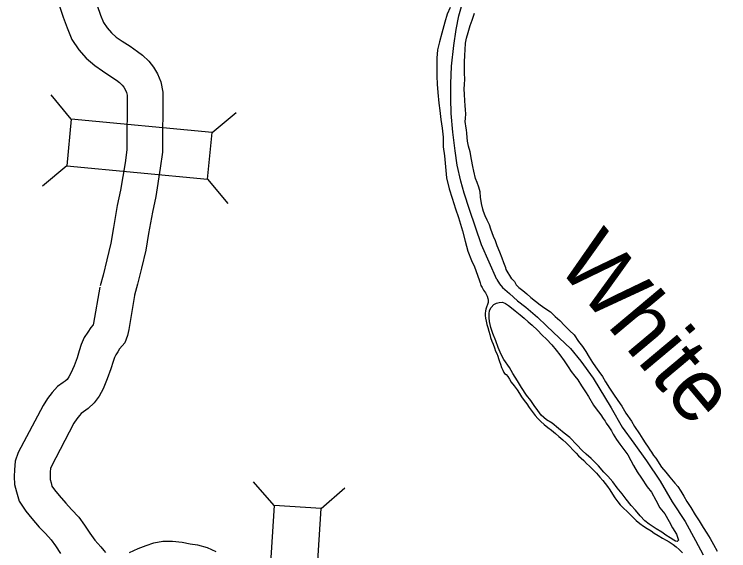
# Model space of a CAD drawing. Extents: x 1377389 to 1380723, y 1168351 to 1170484.
# Drawn here: x 1377843.3 to 1377903.4, y 1169705.3 to 1169750.4 of the extents above; entities that cross this region are included whole.
import ezdxf

# ---------------------------------------------------------------- set-up
doc = ezdxf.new("R2010")
doc.units = 0
doc.layers.add('B_Fill', color=7, linetype='Continuous')

msp = doc.modelspace()

# ---------------------------------------------------------------- linework, layer by layer
at = {"layer": 'B_Fill'}
for p, q in [((1377848.125, 1169741.601), (1377846.442, 1169743.635)), ((1377859.952, 1169740.483), (1377861.986, 1169742.165)), ((1377847.752, 1169737.658), (1377845.718, 1169735.975)), ((1377859.579, 1169736.54), (1377861.262, 1169734.506)), ((1377865.17, 1169709.11), (1377863.426, 1169711.092)), ((1377869.122, 1169708.858), (1377871.104, 1169710.603))]:
    msp.add_line(p, q, dxfattribs=at)
for points in [[(1377847.062, 1169751.354), (1377847.452, 1169750.17), (1377847.773, 1169749.278), (1377848.162, 1169748.289), (1377848.769, 1169747.424), (1377849.376, 1169746.72), (1377850.089, 1169746.099), (1377850.751, 1169745.665), (1377851.374, 1169745.248), (1377851.919, 1169744.863), (1377852.172, 1169744.669), (1377852.397, 1169744.464), (1377852.53, 1169744.285), (1377852.688, 1169744.022), (1377852.769, 1169743.839), (1377852.811, 1169743.604), (1377852.792, 1169739.027), (1377852.637, 1169737.924), (1377852.268, 1169735.637), (1377851.991, 1169734.336), (1377851.661, 1169732.484), (1377851.45, 1169731.174), (1377851.121, 1169729.776), (1377850.789, 1169728.486), (1377850.546, 1169727.593)], [(1377850.289, 1169751.148), (1377850.581, 1169750.335), (1377850.823, 1169749.719), (1377851.138, 1169749.27), (1377851.507, 1169748.842), (1377851.905, 1169748.496), (1377852.408, 1169748.165), (1377853.074, 1169747.72), (1377853.695, 1169747.281), (1377854.098, 1169746.973), (1377854.636, 1169746.482), (1377855.026, 1169745.955), (1377855.353, 1169745.411), (1377855.659, 1169744.724), (1377855.812, 1169743.862), (1377855.792, 1169738.81), (1377855.603, 1169737.475), (1377855.218, 1169735.085), (1377854.936, 1169733.761), (1377854.619, 1169731.982), (1377854.395, 1169730.591), (1377854.034, 1169729.058), (1377853.689, 1169727.719), (1377853.441, 1169726.806)], [(1377883.88, 1169728.123), (1377882.593, 1169731.028), (1377881.579, 1169734.004), (1377881.116, 1169735.373), (1377880.844, 1169736.388), (1377880.531, 1169737.731), (1377880.364, 1169738.929), (1377880.175, 1169740.488), (1377880.045, 1169742.068), (1377880.006, 1169743.321), (1377879.997, 1169744.574), (1377880.06, 1169746.06), (1377880.247, 1169747.781), (1377880.445, 1169749.121), (1377880.669, 1169750.291), (1377881.012, 1169751.456)], [(1377879.956, 1169750.981), (1377879.704, 1169750.411), (1377879.504, 1169749.753), (1377879.264, 1169748.812), (1377879.056, 1169748.104), (1377878.896, 1169747.437), (1377878.839, 1169746.713), (1377878.819, 1169746.061), (1377878.826, 1169745.208), (1377878.857, 1169744.527), (1377878.919, 1169743.827), (1377879.007, 1169742.948), (1377879.077, 1169742.318), (1377879.18, 1169741.579), (1377879.293, 1169740.831), (1377879.367, 1169740.091), (1377879.372, 1169739.269), (1377879.466, 1169738.5), (1377879.644, 1169736.67), (1377879.873, 1169735.745), (1377880.118, 1169734.96), (1377880.396, 1169734.057), (1377880.659, 1169733.323), (1377880.975, 1169732.2), (1377881.222, 1169731.325), (1377881.449, 1169730.49), (1377881.744, 1169729.697), (1377881.99, 1169729.174), (1377882.39, 1169728.082)], [(1377879.956, 1169750.981), (1377879.704, 1169750.411), (1377879.504, 1169749.753), (1377879.264, 1169748.812), (1377879.056, 1169748.104), (1377878.896, 1169747.437), (1377878.839, 1169746.713), (1377878.819, 1169746.061), (1377878.826, 1169745.208), (1377878.857, 1169744.527), (1377878.919, 1169743.827), (1377879.007, 1169742.948), (1377879.077, 1169742.318), (1377879.18, 1169741.579), (1377879.293, 1169740.831), (1377879.367, 1169740.091), (1377879.372, 1169739.269), (1377879.466, 1169738.5), (1377879.644, 1169736.67), (1377879.873, 1169735.745), (1377880.118, 1169734.96), (1377880.396, 1169734.057), (1377880.659, 1169733.323), (1377880.975, 1169732.2), (1377881.222, 1169731.325), (1377881.449, 1169730.49), (1377881.744, 1169729.697), (1377881.99, 1169729.174), (1377882.39, 1169728.082)], [(1377885.13, 1169728.177), (1377884.65, 1169728.948), (1377884.615, 1169729.107), (1377884.452, 1169729.513), (1377884.309, 1169729.91), (1377884.123, 1169730.415), (1377883.907, 1169730.94), (1377883.753, 1169731.356), (1377883.592, 1169731.732), (1377883.382, 1169732.337), (1377883.251, 1169732.704), (1377883.059, 1169733.089), (1377882.896, 1169733.475), (1377882.765, 1169733.831), (1377882.689, 1169734.03), (1377882.574, 1169734.507), (1377882.507, 1169735.047), (1377882.463, 1169735.497), (1377882.371, 1169735.885), (1377882.218, 1169736.271), (1377882.087, 1169736.618), (1377881.949, 1169737.215), (1377881.856, 1169737.613), (1377881.758, 1169738.202), (1377881.628, 1169738.839), (1377881.502, 1169739.327), (1377881.409, 1169739.735), (1377881.38, 1169740.045), (1377881.358, 1169740.425), (1377881.319, 1169740.705), (1377881.295, 1169740.845), (1377881.217, 1169741.394), (1377881.23, 1169741.645), (1377881.257, 1169742.047), (1377881.247, 1169742.367), (1377881.215, 1169742.757), (1377881.193, 1169743.128), (1377881.155, 1169743.708), (1377881.132, 1169744.119), (1377881.159, 1169744.551), (1377881.177, 1169744.932), (1377881.169, 1169745.504), (1377881.144, 1169745.974), (1377881.161, 1169746.386), (1377881.182, 1169746.988), (1377881.199, 1169747.42), (1377881.232, 1169747.973), (1377881.328, 1169748.417), (1377881.474, 1169748.873), (1377881.625, 1169749.46), (1377881.791, 1169749.916), (1377881.993, 1169750.504)], [(1377885.13, 1169728.177), (1377884.65, 1169728.948), (1377884.615, 1169729.107), (1377884.452, 1169729.513), (1377884.309, 1169729.91), (1377884.123, 1169730.415), (1377883.907, 1169730.94), (1377883.753, 1169731.356), (1377883.592, 1169731.732), (1377883.382, 1169732.337), (1377883.251, 1169732.704), (1377883.059, 1169733.089), (1377882.896, 1169733.475), (1377882.765, 1169733.831), (1377882.689, 1169734.03), (1377882.574, 1169734.507), (1377882.507, 1169735.047), (1377882.463, 1169735.497), (1377882.371, 1169735.885), (1377882.218, 1169736.271), (1377882.087, 1169736.618), (1377881.949, 1169737.215), (1377881.856, 1169737.613), (1377881.758, 1169738.202), (1377881.628, 1169738.839), (1377881.502, 1169739.327), (1377881.409, 1169739.735), (1377881.38, 1169740.045), (1377881.358, 1169740.425), (1377881.319, 1169740.705), (1377881.295, 1169740.845), (1377881.217, 1169741.394), (1377881.23, 1169741.645), (1377881.257, 1169742.047), (1377881.247, 1169742.367), (1377881.215, 1169742.757), (1377881.193, 1169743.128), (1377881.155, 1169743.708), (1377881.132, 1169744.119), (1377881.159, 1169744.551), (1377881.177, 1169744.932), (1377881.169, 1169745.504), (1377881.144, 1169745.974), (1377881.161, 1169746.386), (1377881.182, 1169746.988), (1377881.199, 1169747.42), (1377881.232, 1169747.973), (1377881.328, 1169748.417), (1377881.474, 1169748.873), (1377881.625, 1169749.46), (1377881.791, 1169749.916), (1377881.993, 1169750.504)], [(1377882.39, 1169728.082), (1377882.466, 1169727.834), (1377882.542, 1169727.615), (1377882.637, 1169727.427), (1377882.753, 1169727.209), (1377882.909, 1169726.993), (1377883.056, 1169726.726), (1377883.112, 1169726.517), (1377883.145, 1169726.367), (1377883.14, 1169726.177), (1377883.085, 1169726.004), (1377883.011, 1169725.782), (1377882.945, 1169725.609), (1377882.919, 1169725.478), (1377882.894, 1169725.257), (1377882.889, 1169725.096), (1377882.915, 1169724.866), (1377882.972, 1169724.597), (1377883.039, 1169724.338), (1377883.116, 1169724.069), (1377883.194, 1169723.77), (1377883.271, 1169723.502), (1377883.348, 1169723.223), (1377883.456, 1169722.935), (1377883.553, 1169722.666), (1377883.671, 1169722.359), (1377883.768, 1169722.1), (1377883.873, 1169721.893), (1377883.959, 1169721.674), (1377884.025, 1169721.475), (1377884.101, 1169721.217), (1377884.177, 1169720.988), (1377884.265, 1169720.719), (1377884.371, 1169720.482), (1377884.456, 1169720.293), (1377884.528, 1169720.215), (1377884.651, 1169720.118), (1377884.785, 1169719.971), (1377884.931, 1169719.724), (1377885.088, 1169719.488), (1377885.336, 1169719.184), (1377885.585, 1169718.849), (1377885.783, 1169718.534), (1377885.951, 1169718.257), (1377886.179, 1169717.952), (1377886.387, 1169717.657), (1377886.595, 1169717.352), (1377886.854, 1169717.008), (1377887.103, 1169716.683), (1377887.32, 1169716.438), (1377887.567, 1169716.174), (1377887.854, 1169715.911), (1377888.161, 1169715.669), (1377888.457, 1169715.446), (1377888.795, 1169715.164), (1377889.082, 1169714.901), (1377889.429, 1169714.639), (1377889.706, 1169714.366), (1377890.015, 1169714.063), (1377890.262, 1169713.799), (1377890.53, 1169713.506), (1377890.746, 1169713.281), (1377890.951, 1169713.096), (1377891.187, 1169712.881), (1377891.413, 1169712.647), (1377891.66, 1169712.413), (1377892.256, 1169711.827), (1377892.535, 1169711.493), (1377892.772, 1169711.209), (1377893.176, 1169710.708), (1377893.353, 1169710.422), (1377893.603, 1169710.068), (1377893.781, 1169709.751), (1377894.03, 1169709.427), (1377894.237, 1169709.172), (1377894.525, 1169708.879), (1377894.813, 1169708.595), (1377895.018, 1169708.4), (1377895.337, 1169708.088), (1377895.583, 1169707.844), (1377895.89, 1169707.591), (1377896.186, 1169707.379), (1377896.501, 1169707.187), (1377896.827, 1169706.975), (1377897.082, 1169706.781), (1377897.418, 1169706.579), (1377897.784, 1169706.369), (1377898.099, 1169706.196), (1377898.363, 1169706.043), (1377898.699, 1169705.821), (1377898.944, 1169705.637), (1377899.2, 1169705.424), (1377899.458, 1169705.13)], [(1377882.39, 1169728.082), (1377882.466, 1169727.834), (1377882.542, 1169727.615), (1377882.637, 1169727.427), (1377882.753, 1169727.209), (1377882.909, 1169726.993), (1377883.056, 1169726.726), (1377883.112, 1169726.517), (1377883.145, 1169726.367), (1377883.14, 1169726.177), (1377883.085, 1169726.004), (1377883.011, 1169725.782), (1377882.945, 1169725.609), (1377882.919, 1169725.478), (1377882.894, 1169725.257), (1377882.889, 1169725.096), (1377882.915, 1169724.866), (1377882.972, 1169724.597), (1377883.039, 1169724.338), (1377883.116, 1169724.069), (1377883.194, 1169723.77), (1377883.271, 1169723.502), (1377883.348, 1169723.223), (1377883.456, 1169722.935), (1377883.553, 1169722.666), (1377883.671, 1169722.359), (1377883.768, 1169722.1), (1377883.873, 1169721.893), (1377883.959, 1169721.674), (1377884.025, 1169721.475), (1377884.101, 1169721.217), (1377884.177, 1169720.988), (1377884.265, 1169720.719), (1377884.371, 1169720.482), (1377884.456, 1169720.293), (1377884.528, 1169720.215), (1377884.651, 1169720.118), (1377884.785, 1169719.971), (1377884.931, 1169719.724), (1377885.088, 1169719.488), (1377885.336, 1169719.184), (1377885.585, 1169718.849), (1377885.783, 1169718.534), (1377885.951, 1169718.257), (1377886.179, 1169717.952), (1377886.387, 1169717.657), (1377886.595, 1169717.352), (1377886.854, 1169717.008), (1377887.103, 1169716.683), (1377887.32, 1169716.438), (1377887.567, 1169716.174), (1377887.854, 1169715.911), (1377888.161, 1169715.669), (1377888.457, 1169715.446), (1377888.795, 1169715.164), (1377889.082, 1169714.901), (1377889.429, 1169714.639), (1377889.706, 1169714.366), (1377890.015, 1169714.063), (1377890.262, 1169713.799), (1377890.53, 1169713.506), (1377890.746, 1169713.281), (1377890.951, 1169713.096), (1377891.187, 1169712.881), (1377891.413, 1169712.647), (1377891.66, 1169712.413), (1377892.256, 1169711.827), (1377892.535, 1169711.493), (1377892.772, 1169711.209), (1377893.176, 1169710.708), (1377893.353, 1169710.422), (1377893.603, 1169710.068), (1377893.781, 1169709.751), (1377894.03, 1169709.427), (1377894.237, 1169709.172), (1377894.525, 1169708.879), (1377894.813, 1169708.595), (1377895.018, 1169708.4), (1377895.337, 1169708.088), (1377895.583, 1169707.844), (1377895.89, 1169707.591), (1377896.186, 1169707.379), (1377896.501, 1169707.187), (1377896.827, 1169706.975), (1377897.082, 1169706.781), (1377897.418, 1169706.579), (1377897.784, 1169706.369), (1377898.099, 1169706.196), (1377898.363, 1169706.043), (1377898.699, 1169705.821), (1377898.944, 1169705.637), (1377899.2, 1169705.424), (1377899.458, 1169705.13)], [(1377883.88, 1169728.123), (1377884.11, 1169727.758), (1377884.338, 1169727.453), (1377884.923, 1169726.927), (1377885.619, 1169726.314), (1377886.303, 1169725.801), (1377887.297, 1169724.945), (1377888.037, 1169724.212), (1377889.125, 1169723.188), (1377890.068, 1169722.321), (1377890.927, 1169721.251), (1377891.966, 1169719.814), (1377893.483, 1169717.327), (1377894.396, 1169715.697), (1377895.373, 1169714.339), (1377896.443, 1169712.853), (1377897.588, 1169711.148), (1377898.605, 1169709.41), (1377899.68, 1169707.754), (1377900.562, 1169706.163), (1377901.194, 1169704.966)], [(1377885.13, 1169728.177), (1377885.346, 1169727.942), (1377885.493, 1169727.675), (1377885.72, 1169727.43), (1377886.067, 1169727.189), (1377886.394, 1169726.907), (1377886.723, 1169726.605), (1377887.131, 1169726.305), (1377887.52, 1169725.984), (1377887.917, 1169725.704), (1377888.386, 1169725.386), (1377888.777, 1169725.005), (1377889.156, 1169724.654), (1377889.557, 1169724.243), (1377889.989, 1169723.834), (1377890.359, 1169723.453), (1377890.743, 1169722.911), (1377891.055, 1169722.488), (1377891.356, 1169722.065), (1377891.639, 1169721.591), (1377891.921, 1169721.137), (1377892.151, 1169720.782), (1377892.451, 1169720.379), (1377892.763, 1169719.946), (1377893.015, 1169719.512), (1377893.339, 1169718.979), (1377893.673, 1169718.476), (1377894.027, 1169717.934), (1377894.37, 1169717.472), (1377894.715, 1169716.879), (1377895.174, 1169716.199), (1377895.445, 1169715.765), (1377895.852, 1169715.144), (1377896.124, 1169714.69), (1377896.343, 1169714.375), (1377896.572, 1169714.02), (1377896.718, 1169713.793), (1377896.854, 1169713.586), (1377897.041, 1169713.321), (1377897.217, 1169713.085), (1377897.718, 1169712.326), (1377898.059, 1169711.904), (1377898.4, 1169711.501), (1377898.834, 1169710.982), (1377899.072, 1169710.697), (1377899.322, 1169710.303), (1377899.573, 1169709.888), (1377899.845, 1169709.454), (1377900.159, 1169708.951), (1377900.545, 1169708.339), (1377900.869, 1169707.826), (1377901.214, 1169707.264), (1377901.527, 1169706.781), (1377901.789, 1169706.336), (1377902.062, 1169705.842), (1377902.368, 1169705.259)], [(1377885.13, 1169728.177), (1377885.346, 1169727.942), (1377885.493, 1169727.675), (1377885.72, 1169727.43), (1377886.067, 1169727.189), (1377886.394, 1169726.907), (1377886.723, 1169726.605), (1377887.131, 1169726.305), (1377887.52, 1169725.984), (1377887.917, 1169725.704), (1377888.386, 1169725.386), (1377888.777, 1169725.005), (1377889.156, 1169724.654), (1377889.557, 1169724.243), (1377889.989, 1169723.834), (1377890.359, 1169723.453), (1377890.743, 1169722.911), (1377891.055, 1169722.488), (1377891.356, 1169722.065), (1377891.639, 1169721.591), (1377891.921, 1169721.137), (1377892.151, 1169720.782), (1377892.451, 1169720.379), (1377892.763, 1169719.946), (1377893.015, 1169719.512), (1377893.339, 1169718.979), (1377893.673, 1169718.476), (1377894.027, 1169717.934), (1377894.37, 1169717.472), (1377894.715, 1169716.879), (1377895.174, 1169716.199), (1377895.445, 1169715.765), (1377895.852, 1169715.144), (1377896.124, 1169714.69), (1377896.343, 1169714.375), (1377896.572, 1169714.02), (1377896.718, 1169713.793), (1377896.854, 1169713.586), (1377897.041, 1169713.321), (1377897.217, 1169713.085), (1377897.718, 1169712.326), (1377898.059, 1169711.904), (1377898.4, 1169711.501), (1377898.834, 1169710.982), (1377899.072, 1169710.697), (1377899.322, 1169710.303), (1377899.573, 1169709.888), (1377899.845, 1169709.454), (1377900.159, 1169708.951), (1377900.545, 1169708.339), (1377900.869, 1169707.826), (1377901.214, 1169707.264), (1377901.527, 1169706.781), (1377901.789, 1169706.336), (1377902.062, 1169705.842), (1377902.368, 1169705.259)], [(1377850.515, 1169727.455), (1377849.996, 1169724.453), (1377849.968, 1169724.304), (1377849.773, 1169724.08), (1377849.521, 1169723.685), (1377849.217, 1169723.233), (1377848.957, 1169722.646), (1377848.776, 1169722.117), (1377848.607, 1169721.538), (1377848.357, 1169720.861), (1377848.088, 1169720.229), (1377847.925, 1169719.928), (1377847.766, 1169719.715), (1377847.616, 1169719.566), (1377847.442, 1169719.445), (1377846.971, 1169719.121), (1377846.506, 1169718.613), (1377846.116, 1169718.098), (1377845.754, 1169717.527), (1377843.658, 1169713.563), (1377843.41, 1169712.835), (1377843.356, 1169712.122), (1377843.335, 1169711.548), (1377843.367, 1169710.87), (1377843.519, 1169710.249), (1377843.736, 1169709.47), (1377844.309, 1169708.628), (1377844.807, 1169708.023), (1377845.437, 1169707.291), (1377845.947, 1169706.746), (1377846.433, 1169706.215), (1377846.792, 1169705.724), (1377847.226, 1169705.08)], [(1377853.471, 1169726.944), (1377852.948, 1169723.919), (1377852.852, 1169723.412), (1377852.62, 1169722.783), (1377852.183, 1169722.279), (1377852.03, 1169722.04), (1377851.853, 1169721.777), (1377851.754, 1169721.552), (1377851.637, 1169721.211), (1377851.457, 1169720.596), (1377851.146, 1169719.753), (1377850.793, 1169718.924), (1377850.46, 1169718.309), (1377850.038, 1169717.743), (1377849.545, 1169717.253), (1377849.149, 1169716.977), (1377848.952, 1169716.842), (1377848.813, 1169716.691), (1377848.584, 1169716.387), (1377848.35, 1169716.02), (1377846.421, 1169712.37), (1377846.372, 1169712.228), (1377846.352, 1169711.955), (1377846.338, 1169711.565), (1377846.35, 1169711.302), (1377846.423, 1169711.006), (1377846.494, 1169710.749), (1377846.712, 1169710.429), (1377847.103, 1169709.955), (1377847.67, 1169709.295), (1377848.149, 1169708.783), (1377848.756, 1169708.12), (1377849.247, 1169707.449), (1377849.689, 1169706.794), (1377850.111, 1169706.206), (1377850.592, 1169705.629), (1377850.844, 1169705.315), (1377851.006, 1169705.157)], [(1377891.996, 1169717.538), (1377892.141, 1169717.341), (1377892.411, 1169716.977), (1377892.597, 1169716.732), (1377892.805, 1169716.426), (1377892.982, 1169716.2), (1377893.066, 1169716.042), (1377893.284, 1169715.737), (1377893.503, 1169715.402), (1377893.641, 1169715.115), (1377893.913, 1169714.671), (1377894.204, 1169714.257), (1377894.555, 1169713.825), (1377894.867, 1169713.382), (1377895.131, 1169712.888), (1377895.361, 1169712.483), (1377895.666, 1169711.929), (1377896.02, 1169711.397), (1377896.49, 1169710.687), (1377896.852, 1169710.226), (1377897.22, 1169709.563), (1377897.567, 1169708.921), (1377897.991, 1169708.411), (1377898.348, 1169707.768), (1377898.622, 1169707.244), (1377898.956, 1169706.701), (1377899.14, 1169706.195), (1377899.033, 1169706.071), (1377898.892, 1169706.098), (1377898.729, 1169706.193), (1377898.444, 1169706.386), (1377898.078, 1169706.617), (1377897.721, 1169706.858), (1377897.263, 1169707.147), (1377896.662, 1169707.532), (1377896.304, 1169707.833), (1377895.913, 1169708.254), (1377895.531, 1169708.705), (1377895.159, 1169709.116), (1377894.745, 1169709.637), (1377894.413, 1169710.079), (1377893.989, 1169710.6), (1377893.626, 1169711.091), (1377893.203, 1169711.582), (1377892.854, 1169711.923), (1377892.409, 1169712.453), (1377891.783, 1169713.058), (1377891.373, 1169713.418), (1377891.054, 1169713.74), (1377890.581, 1169714.209), (1377890.014, 1169714.836), (1377889.535, 1169715.184), (1377889.044, 1169715.582), (1377888.512, 1169716.029), (1377888.033, 1169716.327), (1377887.583, 1169716.706), (1377887.303, 1169717.09), (1377887.001, 1169717.523), (1377886.72, 1169717.947), (1377886.367, 1169718.399), (1377885.95, 1169719.04), (1377885.606, 1169719.582), (1377885.209, 1169720.223), (1377884.945, 1169720.728), (1377884.468, 1169721.377), (1377884.226, 1169721.802), (1377883.981, 1169722.387), (1377883.776, 1169722.943), (1377883.549, 1169723.579), (1377883.376, 1169724.076), (1377883.253, 1169724.574), (1377883.234, 1169724.895), (1377883.216, 1169725.216), (1377883.268, 1169725.518), (1377883.392, 1169725.762), (1377883.625, 1169726.009), (1377883.833, 1169726.115), (1377884.081, 1169726.192), (1377884.351, 1169726.209), (1377884.614, 1169726.086), (1377884.849, 1169725.932), (1377885.114, 1169725.718), (1377885.401, 1169725.485), (1377885.82, 1169725.136), (1377886.168, 1169724.854), (1377886.516, 1169724.562), (1377886.844, 1169724.28), (1377887.286, 1169723.841), (1377887.687, 1169723.43), (1377888.036, 1169723.099), (1377888.479, 1169722.619), (1377888.851, 1169722.168), (1377889.152, 1169721.775), (1377889.525, 1169721.283), (1377889.858, 1169720.781), (1377890.119, 1169720.386), (1377890.43, 1169719.983), (1377890.668, 1169719.669), (1377890.982, 1169719.176), (1377891.325, 1169718.673), (1377891.585, 1169718.289)], [(1377891.996, 1169717.538), (1377892.141, 1169717.341), (1377892.411, 1169716.977), (1377892.597, 1169716.732), (1377892.805, 1169716.426), (1377892.982, 1169716.2), (1377893.066, 1169716.042), (1377893.284, 1169715.737), (1377893.503, 1169715.402), (1377893.641, 1169715.115), (1377893.913, 1169714.671), (1377894.204, 1169714.257), (1377894.555, 1169713.825), (1377894.867, 1169713.382), (1377895.131, 1169712.888), (1377895.361, 1169712.483), (1377895.666, 1169711.929), (1377896.02, 1169711.397), (1377896.49, 1169710.687), (1377896.852, 1169710.226), (1377897.22, 1169709.563), (1377897.567, 1169708.921), (1377897.991, 1169708.411), (1377898.348, 1169707.768), (1377898.622, 1169707.244), (1377898.956, 1169706.701), (1377899.14, 1169706.195), (1377899.033, 1169706.071), (1377898.892, 1169706.098), (1377898.729, 1169706.193), (1377898.444, 1169706.386), (1377898.078, 1169706.617), (1377897.721, 1169706.858), (1377897.263, 1169707.147), (1377896.662, 1169707.532), (1377896.304, 1169707.833), (1377895.913, 1169708.254), (1377895.531, 1169708.705), (1377895.159, 1169709.116), (1377894.745, 1169709.637), (1377894.413, 1169710.079), (1377893.989, 1169710.6), (1377893.626, 1169711.091), (1377893.203, 1169711.582), (1377892.854, 1169711.923), (1377892.409, 1169712.453), (1377891.783, 1169713.058), (1377891.373, 1169713.418), (1377891.054, 1169713.74), (1377890.581, 1169714.209), (1377890.014, 1169714.836), (1377889.535, 1169715.184), (1377889.044, 1169715.582), (1377888.512, 1169716.029), (1377888.033, 1169716.327), (1377887.583, 1169716.706), (1377887.303, 1169717.09), (1377887.001, 1169717.523), (1377886.72, 1169717.947), (1377886.367, 1169718.399), (1377885.95, 1169719.04), (1377885.606, 1169719.582), (1377885.209, 1169720.223), (1377884.945, 1169720.728), (1377884.468, 1169721.377), (1377884.226, 1169721.802), (1377883.981, 1169722.387), (1377883.776, 1169722.943), (1377883.549, 1169723.579), (1377883.376, 1169724.076), (1377883.253, 1169724.574), (1377883.234, 1169724.895), (1377883.216, 1169725.216), (1377883.268, 1169725.518), (1377883.392, 1169725.762), (1377883.625, 1169726.009), (1377883.833, 1169726.115), (1377884.081, 1169726.192), (1377884.351, 1169726.209), (1377884.614, 1169726.086), (1377884.849, 1169725.932), (1377885.114, 1169725.718), (1377885.401, 1169725.485), (1377885.82, 1169725.136), (1377886.168, 1169724.854), (1377886.516, 1169724.562), (1377886.844, 1169724.28), (1377887.286, 1169723.841), (1377887.687, 1169723.43), (1377888.036, 1169723.099), (1377888.479, 1169722.619), (1377888.851, 1169722.168), (1377889.152, 1169721.775), (1377889.525, 1169721.283), (1377889.858, 1169720.781), (1377890.119, 1169720.386), (1377890.43, 1169719.983), (1377890.668, 1169719.669), (1377890.982, 1169719.176), (1377891.325, 1169718.673), (1377891.585, 1169718.289)], [(1377891.585, 1169718.289), (1377891.996, 1169717.538)], [(1377891.585, 1169718.289), (1377891.996, 1169717.538)], [(1377853.026, 1169705.165), (1377853.73, 1169705.493), (1377854.415, 1169705.75), (1377855.069, 1169705.967), (1377855.817, 1169706.103), (1377856.624, 1169706.112), (1377857.428, 1169706.035), (1377858.114, 1169705.901), (1377858.728, 1169705.797), (1377859.525, 1169705.585), (1377860.27, 1169705.254)]]:
    msp.add_lwpolyline(points, dxfattribs=at)
for points in [[(1377847.752, 1169737.658), (1377859.579, 1169736.54), (1377859.952, 1169740.483), (1377848.125, 1169741.601)], [(1377865.17, 1169709.11), (1377864.414, 1169697.254), (1377868.366, 1169697.003), (1377869.122, 1169708.858)]]:
    msp.add_lwpolyline(points, close=True, dxfattribs=at)

# ---------------------------------------------------------------- texts
msp.add_text('White', height=5.28, rotation=310, dxfattribs=at).set_placement((1377888.789, 1169729.338))

doc.saveas('drawing.dxf')
